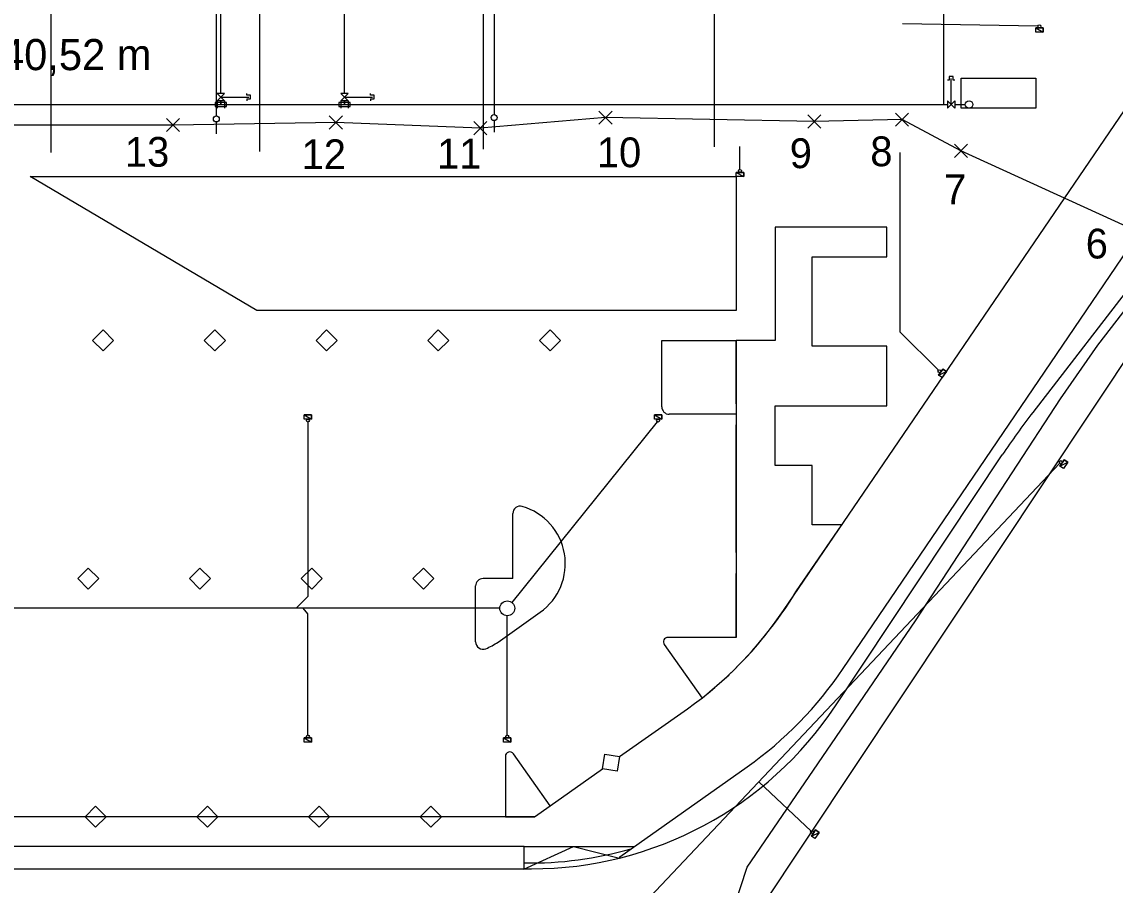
# Model space of a CAD drawing. Extents: x -263995 to -263575, y -1242437 to -1242140.
# Drawn here: x -263850 to -263776.6, y -1242302.6 to -1242244.6 of the extents above; entities that cross this region are included whole.
import ezdxf

# ---------------------------------------------------------------- set-up
doc = ezdxf.new("R2010")
doc.units = 0
for name, color, linetype in [('DELTA_ONLINE_JESTVUJUCA_TRASA', 7, 'Continuous'), ('KFA_2D_SITUACIA_DSP', 7, 'Continuous'), ('KFA_BODY', 7, 'Continuous'), ('KFA_SO_63-3_PRELOZKA_DELTA_ONLINE_TRASA', 7, 'Continuous'), ('POPIS', 7, 'Continuous')]:
    doc.layers.add(name, color=color, linetype=linetype)

msp = doc.modelspace()

# ---------------------------------------------------------------- linework, layer by layer
at = {"layer": 'DELTA_ONLINE_JESTVUJUCA_TRASA'}
for p, q in [((-263777.8, -1242266.3), (-263773.12, -1242260.22)), ((-263780.3, -1242269.92), (-263777.8, -1242266.3)), ((-263790.03, -1242284.82), (-263780.3, -1242269.92)), ((-263795.68, -1242293.09), (-263790.03, -1242284.82)), ((-263801.33, -1242301.36), (-263795.68, -1242293.09)), ((-263802.26, -1242304.18), (-263801.33, -1242301.36))]:
    msp.add_line(p, q, dxfattribs=at)
at = {"layer": 'KFA_2D_SITUACIA_DSP'}
for p, q in [((-263788.143, -1242250.14), (-263788.143, -1242140.046)), ((-263822.88, -1242337.914), (-263734.49, -1242204.937)), ((-263794.898, -1242288.032), (-263742.736, -1242211.145)), ((-263798.899, -1242284.125), (-263751.864, -1242215.081)), ((-263752.521, -1242232.37), (-263782.166, -1242270.821)), ((-263836.968, -1242235.757), (-263836.969, -1242250.909)), ((-263836.668, -1242249.39), (-263836.668, -1242235.757)), ((-263828.368, -1242249.39), (-263828.368, -1242235.757)), ((-263818.318, -1242235.757), (-263818.321, -1242250.822)), ((-263803.556, -1242238.308), (-263803.556, -1242252.989)), ((-263848.068, -1242241.132), (-263848.068, -1242253.366)), ((-263834.068, -1242241.132), (-263834.068, -1242253.298)), ((-263819.068, -1242241.132), (-263819.068, -1242253.146)), ((-263781.818, -1242244.885), (-263790.914, -1242244.718)), ((-263781.968, -1242244.987), (-263781.468, -1242244.987)), ((-263781.968, -1242245.277), (-263781.968, -1242244.987)), ((-263781.968, -1242244.987), (-263781.468, -1242245.277)), ((-263781.968, -1242244.987), (-263781.468, -1242245.277)), ((-263781.468, -1242244.987), (-263781.968, -1242244.987)), ((-263781.468, -1242245.277), (-263781.968, -1242245.277)), ((-263781.468, -1242244.987), (-263781.468, -1242245.277)), ((-263781.468, -1242245.277), (-263781.468, -1242244.987)), ((-263787.768, -1242248.265), (-263787.768, -1242248.515)), ((-263787.518, -1242248.265), (-263787.768, -1242248.265)), ((-263787.643, -1242250.14), (-263787.643, -1242248.39)), ((-263787.518, -1242248.515), (-263787.518, -1242248.265)), ((-263786.968, -1242248.382), (-263781.968, -1242248.382)), ((-263786.968, -1242250.382), (-263786.968, -1242248.382)), ((-263781.968, -1242248.382), (-263781.968, -1242250.382)), ((-263787.768, -1242248.515), (-263787.893, -1242248.515)), ((-263787.393, -1242248.515), (-263787.518, -1242248.515)), ((-263836.418, -1242249.39), (-263836.918, -1242249.39)), ((-263836.918, -1242249.89), (-263836.418, -1242249.39)), ((-263836.918, -1242249.39), (-263836.418, -1242249.89)), ((-263836.418, -1242249.89), (-263836.918, -1242249.89)), ((-263836.918, -1242249.89), (-263836.918, -1242250.39)), ((-263836.668, -1242249.64), (-263834.793, -1242249.64)), ((-263836.668, -1242250.14), (-263836.668, -1242249.89)), ((-263836.668, -1242249.89), (-263836.668, -1242250.14)), ((-263836.418, -1242249.89), (-263836.418, -1242250.39)), ((-263834.918, -1242249.515), (-263834.918, -1242249.39)), ((-263834.668, -1242249.515), (-263834.918, -1242249.515)), ((-263834.918, -1242249.765), (-263834.918, -1242249.89)), ((-263834.918, -1242249.765), (-263834.668, -1242249.765)), ((-263834.668, -1242249.765), (-263834.668, -1242249.515)), ((-263828.118, -1242249.39), (-263828.618, -1242249.39)), ((-263828.618, -1242249.89), (-263828.118, -1242249.39)), ((-263828.618, -1242249.39), (-263828.118, -1242249.89)), ((-263828.118, -1242249.89), (-263828.618, -1242249.89)), ((-263828.618, -1242249.89), (-263828.618, -1242250.39)), ((-263828.368, -1242249.64), (-263826.493, -1242249.64)), ((-263828.368, -1242250.14), (-263828.368, -1242249.89)), ((-263828.368, -1242249.89), (-263828.368, -1242250.14)), ((-263828.118, -1242249.89), (-263828.118, -1242250.39)), ((-263826.618, -1242249.515), (-263826.618, -1242249.39)), ((-263826.368, -1242249.515), (-263826.618, -1242249.515)), ((-263826.618, -1242249.765), (-263826.618, -1242249.89)), ((-263826.618, -1242249.765), (-263826.368, -1242249.765)), ((-263826.368, -1242249.765), (-263826.368, -1242249.515)), ((-263787.893, -1242250.39), (-263787.393, -1242249.89)), ((-263787.893, -1242249.89), (-263787.893, -1242250.39)), ((-263787.393, -1242250.39), (-263787.893, -1242249.89)), ((-263787.393, -1242249.89), (-263787.393, -1242250.39)), ((-263924.143, -1242250.14), (-263788.143, -1242250.14)), ((-263836.293, -1242250.015), (-263837.043, -1242250.015)), ((-263837.043, -1242250.015), (-263837.043, -1242250.265)), ((-263837.043, -1242250.265), (-263836.293, -1242250.265)), ((-263836.293, -1242250.265), (-263836.293, -1242250.015)), ((-263827.993, -1242250.015), (-263828.743, -1242250.015)), ((-263828.743, -1242250.015), (-263828.743, -1242250.265)), ((-263828.743, -1242250.265), (-263827.993, -1242250.265)), ((-263827.993, -1242250.265), (-263827.993, -1242250.015)), ((-263788.143, -1242250.14), (-263787.893, -1242250.14)), ((-263788.143, -1242250.14), (-263787.893, -1242250.14)), ((-263787.393, -1242250.14), (-263786.693, -1242250.14)), ((-263781.968, -1242250.382), (-263786.968, -1242250.382)), ((-263836.969, -1242251.309), (-263836.969, -1242252.109)), ((-263818.322, -1242251.222), (-263818.322, -1242252.009)), ((-263801.822, -1242254.497), (-263801.837, -1242252.972)), ((-263791.063, -1242265.427), (-263791.063, -1242253.362)), ((-263834.256, -1242263.984), (-263849.468, -1242254.985)), ((-263849.468, -1242254.985), (-263802.068, -1242254.987)), ((-263802.071, -1242254.697), (-263801.571, -1242254.697)), ((-263802.071, -1242254.987), (-263802.071, -1242254.697)), ((-263802.071, -1242254.697), (-263801.571, -1242254.987)), ((-263802.071, -1242254.697), (-263801.571, -1242254.987)), ((-263801.571, -1242254.697), (-263802.071, -1242254.697)), ((-263801.571, -1242254.987), (-263802.071, -1242254.987)), ((-263802.068, -1242254.987), (-263802.068, -1242263.988)), ((-263801.571, -1242254.697), (-263801.571, -1242254.987)), ((-263801.571, -1242254.987), (-263801.571, -1242254.697)), ((-263802.068, -1242263.988), (-263834.256, -1242263.984)), ((-263845.275, -1242265.986), (-263844.568, -1242265.279)), ((-263844.568, -1242265.279), (-263843.861, -1242265.986)), ((-263837.775, -1242265.986), (-263837.068, -1242265.279)), ((-263837.068, -1242265.279), (-263836.361, -1242265.986)), ((-263830.275, -1242265.986), (-263829.568, -1242265.279)), ((-263829.568, -1242265.279), (-263828.861, -1242265.986)), ((-263822.775, -1242265.986), (-263822.068, -1242265.279)), ((-263822.068, -1242265.279), (-263821.361, -1242265.986)), ((-263815.275, -1242265.986), (-263814.568, -1242265.279)), ((-263814.568, -1242265.279), (-263813.861, -1242265.986)), ((-263844.568, -1242266.693), (-263845.275, -1242265.986)), ((-263843.861, -1242265.986), (-263844.568, -1242266.693)), ((-263837.068, -1242266.693), (-263837.775, -1242265.986)), ((-263836.361, -1242265.986), (-263837.068, -1242266.693)), ((-263829.568, -1242266.693), (-263830.275, -1242265.986)), ((-263828.861, -1242265.986), (-263829.568, -1242266.693)), ((-263822.068, -1242266.694), (-263822.775, -1242265.986)), ((-263821.361, -1242265.986), (-263822.068, -1242266.694)), ((-263814.568, -1242266.693), (-263815.275, -1242265.986)), ((-263813.861, -1242265.986), (-263814.568, -1242266.693)), ((-263807.068, -1242270.447), (-263807.068, -1242265.987)), ((-263807.068, -1242265.987), (-263802.068, -1242265.987)), ((-263802.068, -1242270.24), (-263802.068, -1242265.987)), ((-263788.502, -1242267.989), (-263791.063, -1242265.427)), ((-263788.491, -1242268.322), (-263788.207, -1242267.91)), ((-263788.207, -1242267.91), (-263788.491, -1242268.322)), ((-263788.491, -1242268.322), (-263787.968, -1242268.075)), ((-263788.491, -1242268.322), (-263787.968, -1242268.075)), ((-263787.968, -1242268.075), (-263788.252, -1242268.487)), ((-263788.207, -1242267.91), (-263787.968, -1242268.075)), ((-263787.968, -1242268.075), (-263788.207, -1242267.91)), ((-263788.252, -1242268.487), (-263788.491, -1242268.322)), ((-263831.074, -1242270.983), (-263830.574, -1242270.983)), ((-263831.074, -1242271.273), (-263831.074, -1242270.983)), ((-263831.074, -1242270.983), (-263830.574, -1242271.273)), ((-263831.074, -1242270.983), (-263830.574, -1242271.273)), ((-263830.574, -1242270.983), (-263831.074, -1242270.983)), ((-263830.574, -1242270.983), (-263830.574, -1242271.273)), ((-263830.574, -1242271.273), (-263830.574, -1242270.983)), ((-263807.568, -1242270.982), (-263807.068, -1242270.982)), ((-263807.568, -1242271.272), (-263807.568, -1242270.982)), ((-263807.568, -1242270.982), (-263807.068, -1242271.272)), ((-263807.568, -1242270.982), (-263807.068, -1242271.272)), ((-263807.068, -1242270.982), (-263807.568, -1242270.982)), ((-263807.068, -1242270.982), (-263807.068, -1242271.272)), ((-263807.068, -1242271.272), (-263807.068, -1242270.982)), ((-263802.068, -1242270.947), (-263806.568, -1242270.947)), ((-263830.574, -1242271.273), (-263831.074, -1242271.273)), ((-263830.824, -1242271.473), (-263830.824, -1242283.187)), ((-263807.38, -1242271.45), (-263817.128, -1242283.593)), ((-263807.068, -1242271.272), (-263807.568, -1242271.272)), ((-263802.068, -1242280.24), (-263802.068, -1242271.654)), ((-263795.416, -1242290.541), (-263784.214, -1242273.68)), ((-263780.34, -1242274.426), (-263780.062, -1242274.011)), ((-263780.062, -1242274.011), (-263780.34, -1242274.426)), ((-263780.062, -1242274.011), (-263779.821, -1242274.173)), ((-263779.821, -1242274.173), (-263780.062, -1242274.011)), ((-263780.353, -1242274.236), (-263808.248, -1242303.783)), ((-263780.34, -1242274.426), (-263779.821, -1242274.173)), ((-263780.34, -1242274.426), (-263779.821, -1242274.173)), ((-263780.099, -1242274.588), (-263780.34, -1242274.426)), ((-263779.821, -1242274.173), (-263780.099, -1242274.588)), ((-263817.068, -1242281.982), (-263817.068, -1242277.62)), ((-263846.275, -1242281.982), (-263845.568, -1242281.275)), ((-263845.568, -1242281.275), (-263844.861, -1242281.982)), ((-263838.775, -1242281.982), (-263838.068, -1242281.275)), ((-263838.068, -1242281.275), (-263837.361, -1242281.982)), ((-263831.275, -1242281.982), (-263830.568, -1242281.275)), ((-263830.568, -1242281.275), (-263829.861, -1242281.982)), ((-263823.775, -1242281.982), (-263823.068, -1242281.275)), ((-263823.068, -1242281.275), (-263822.361, -1242281.982)), ((-263845.568, -1242282.689), (-263846.275, -1242281.982)), ((-263844.861, -1242281.982), (-263845.568, -1242282.689)), ((-263838.068, -1242282.689), (-263838.775, -1242281.982)), ((-263837.361, -1242281.982), (-263838.068, -1242282.689)), ((-263830.568, -1242282.689), (-263831.275, -1242281.982)), ((-263829.861, -1242281.982), (-263830.568, -1242282.689)), ((-263823.068, -1242282.689), (-263823.775, -1242281.982)), ((-263822.361, -1242281.982), (-263823.068, -1242282.689)), ((-263817.068, -1242281.982), (-263819.068, -1242281.982)), ((-263802.068, -1242285.947), (-263802.068, -1242281.654)), ((-263819.568, -1242286.231), (-263819.568, -1242282.482)), ((-263830.824, -1242283.187), (-263831.619, -1242283.982)), ((-263817.941, -1242283.982), (-263870.324, -1242283.982)), ((-263817.941, -1242283.982), (-263870.324, -1242283.982)), ((-263830.824, -1242284.343), (-263831.149, -1242283.982)), ((-263830.824, -1242292.492), (-263830.824, -1242284.343)), ((-263818.06, -1242286.248), (-263815.232, -1242284.248)), ((-263817.441, -1242292.492), (-263817.441, -1242284.482)), ((-263809.895, -1242293.947), (-263805.344, -1242290.728)), ((-263831.074, -1242292.693), (-263830.574, -1242292.693)), ((-263831.074, -1242292.983), (-263831.074, -1242292.693)), ((-263831.074, -1242292.693), (-263830.574, -1242292.983)), ((-263831.074, -1242292.693), (-263830.574, -1242292.983)), ((-263830.574, -1242292.693), (-263831.074, -1242292.693)), ((-263830.574, -1242292.983), (-263831.074, -1242292.983)), ((-263830.824, -1242292.693), (-263830.824, -1242292.692)), ((-263830.574, -1242292.693), (-263830.574, -1242292.983)), ((-263830.574, -1242292.983), (-263830.574, -1242292.693)), ((-263817.691, -1242292.692), (-263817.191, -1242292.692)), ((-263817.691, -1242292.982), (-263817.691, -1242292.692)), ((-263817.691, -1242292.692), (-263817.191, -1242292.982)), ((-263817.691, -1242292.692), (-263817.191, -1242292.982)), ((-263817.191, -1242292.692), (-263817.691, -1242292.692)), ((-263817.191, -1242292.982), (-263817.691, -1242292.982)), ((-263817.191, -1242292.692), (-263817.191, -1242292.982)), ((-263817.191, -1242292.982), (-263817.191, -1242292.692)), ((-263811.05, -1242294.763), (-263810.881, -1242293.778)), ((-263810.881, -1242293.778), (-263809.895, -1242293.947)), ((-263809.895, -1242293.947), (-263810.064, -1242294.932)), ((-263809.875, -1242300.669), (-263801.342, -1242294.634)), ((-263814.555, -1242297.242), (-263811.05, -1242294.763)), ((-263810.064, -1242294.932), (-263811.05, -1242294.763)), ((-263797.048, -1242298.952), (-263800.558, -1242295.638)), ((-263845.775, -1242297.982), (-263845.068, -1242297.275)), ((-263845.068, -1242297.275), (-263844.361, -1242297.982)), ((-263838.275, -1242297.982), (-263837.568, -1242297.275)), ((-263837.568, -1242297.275), (-263836.861, -1242297.982)), ((-263830.775, -1242297.982), (-263830.068, -1242297.275)), ((-263830.068, -1242297.275), (-263829.361, -1242297.982)), ((-263823.275, -1242297.982), (-263822.568, -1242297.275)), ((-263822.568, -1242297.275), (-263821.861, -1242297.982)), ((-263815.601, -1242297.982), (-263917.08, -1242297.982)), ((-263845.068, -1242298.689), (-263845.775, -1242297.982)), ((-263844.361, -1242297.982), (-263845.068, -1242298.689)), ((-263837.568, -1242298.689), (-263838.275, -1242297.982)), ((-263836.861, -1242297.982), (-263837.568, -1242298.689)), ((-263830.068, -1242298.689), (-263830.775, -1242297.982)), ((-263829.361, -1242297.982), (-263830.068, -1242298.689)), ((-263822.568, -1242298.689), (-263823.275, -1242297.982)), ((-263821.861, -1242297.982), (-263822.568, -1242298.689)), ((-263797.029, -1242299.286), (-263796.75, -1242298.871)), ((-263796.75, -1242298.871), (-263797.029, -1242299.286)), ((-263797.029, -1242299.286), (-263796.51, -1242299.032)), ((-263797.029, -1242299.286), (-263796.51, -1242299.032)), ((-263796.51, -1242299.032), (-263796.788, -1242299.448)), ((-263796.75, -1242298.871), (-263796.51, -1242299.032)), ((-263796.51, -1242299.032), (-263796.75, -1242298.871)), ((-263796.788, -1242299.448), (-263797.029, -1242299.286)), ((-263816.308, -1242299.982), (-263918.049, -1242299.982)), ((-263816.327, -1242301.51), (-263813.002, -1242299.982)), ((-263816.308, -1242301.482), (-263816.308, -1242299.982)), ((-263816.308, -1242299.982), (-263808.904, -1242299.982)), ((-263813.002, -1242299.982), (-263809.906, -1242300.757)), ((-263809.906, -1242300.757), (-263809.875, -1242300.669)), ((-263914.08, -1242301.482), (-263815.822, -1242301.482))]:
    msp.add_line(p, q, dxfattribs=at)
for points in [[(-263798.064, -1242282.882), (-263794.987, -1242278.383), (-263796.968, -1242278.382), (-263796.968, -1242274.382), (-263799.468, -1242274.382), (-263799.468, -1242270.382), (-263791.968, -1242270.382), (-263791.968, -1242266.382), (-263796.968, -1242266.382), (-263796.968, -1242260.382), (-263791.968, -1242260.382), (-263791.968, -1242258.382), (-263799.468, -1242258.382), (-263799.468, -1242265.987), (-263802.068, -1242265.987)], [(-263802.068, -1242265.987), (-263802.068, -1242270.24), (-263802.068, -1242270.947), (-263802.068, -1242271.654), (-263802.068, -1242273.447), (-263802.068, -1242275.947), (-263802.068, -1242278.447), (-263802.068, -1242280.24), (-263802.068, -1242280.24), (-263802.068, -1242281.654), (-263802.068, -1242283.447), (-263802.068, -1242285.947), (-263806.656, -1242285.943)], [(-263806.901, -1242286.416), (-263804.349, -1242290.024), (-263802.552, -1242288.44)], [(-263817.568, -1242293.926), (-263817.568, -1242297.982), (-263815.601, -1242297.982), (-263814.555, -1242297.242), (-263817.023, -1242293.753)]]:
    msp.add_lwpolyline(points, dxfattribs=at)
for centre, radius in [((-263781.718, -1242244.887), 0.1), ((-263786.443, -1242250.14), 0.25), ((-263836.969, -1242251.109), 0.2), ((-263818.322, -1242251.022), 0.2), ((-263801.821, -1242254.597), 0.1), ((-263788.431, -1242268.059), 0.1), ((-263830.824, -1242271.373), 0.1), ((-263807.318, -1242271.372), 0.1), ((-263780.284, -1242274.163), 0.1), ((-263817.441, -1242283.982), 0.5), ((-263830.824, -1242292.592), 0.1), ((-263817.441, -1242292.592), 0.1), ((-263796.975, -1242299.02), 0.1)]:
    msp.add_circle(centre, radius, dxfattribs=at)
for centre, radius, start, end in [((-263806.568, -1242270.447), 0.5, 180, 270), ((-263742.568, -1242301.35), 50, 142.36875, 146.39918), ((-263816.568, -1242277.62), 0.5, 73.84458, 180), ((-263817.542, -1242280.982), 4, 305.27024, 73.84458), ((-263819.068, -1242282.482), 0.5, 90, 180), ((-263821.806, -1242268.304), 27.86, 313.71918, 328.45017), ((-263820.069, -1242269.909), 25.5, 305.27024, 326.11647), ((-263819.068, -1242286.231), 0.5, 180, 291.83316), ((-263820.369, -1242282.982), 4, 291.83316, 305.27024), ((-263806.656, -1242286.243), 0.3, 89.94357, 215.27024), ((-263816.067, -1242273.815), 25.5, 305.27024, 326.11647), ((-263815.822, -1242276.982), 24.5, 270, 326.39918), ((-263817.268, -1242293.926), 0.3, 35.27024, 180), ((-263815.836, -1242276.967), 24.119, 268.87866, 286.17976)]:
    msp.add_arc(centre, radius, start, end, dxfattribs=at)
at = {"layer": 'KFA_BODY'}
for p, q in [((-263811.285, -1242251.461), (-263810.401, -1242250.577)), ((-263810.401, -1242251.461), (-263811.285, -1242250.577)), ((-263840.315, -1242251.962), (-263839.431, -1242251.078)), ((-263839.431, -1242251.962), (-263840.315, -1242251.078)), ((-263829.39, -1242251.795), (-263828.506, -1242250.911)), ((-263828.506, -1242251.795), (-263829.39, -1242250.911)), ((-263819.691, -1242252.171), (-263818.807, -1242251.287)), ((-263818.807, -1242252.171), (-263819.691, -1242251.287)), ((-263797.273, -1242251.724), (-263796.389, -1242250.84)), ((-263796.389, -1242251.724), (-263797.273, -1242250.84)), ((-263791.382, -1242251.597), (-263790.498, -1242250.713)), ((-263790.498, -1242251.597), (-263791.382, -1242250.713)), ((-263787.431, -1242253.693), (-263786.547, -1242252.809)), ((-263786.547, -1242253.693), (-263787.431, -1242252.809))]:
    msp.add_line(p, q, dxfattribs=at)
at = {"layer": 'KFA_SO_63-3_PRELOZKA_DELTA_ONLINE_TRASA'}
for points in [[(-263786.989, -1242253.251), (-263790.94, -1242251.155), (-263796.831, -1242251.282), (-263810.843, -1242251.019), (-263819.249, -1242251.729), (-263828.948, -1242251.353), (-263839.873, -1242251.52), (-263855.379, -1242251.533), (-263870.851, -1242251.493), (-263884.513, -1242251.425), (-263895.724, -1242251.49), (-263903.83, -1242251.49), (-263915.205, -1242251.485), (-263919.446, -1242251.469)], [(-263770.383, -1242255.549), (-263772.055, -1242258.017), (-263773.15, -1242258.989), (-263774.214, -1242259.11), (-263775.866, -1242258.328), (-263786.989, -1242253.251)]]:
    msp.add_lwpolyline(points, dxfattribs=at)

# ---------------------------------------------------------------- texts
at = {"layer": 'KFA_BODY'}
for s, p in [('13', (-263843.102, -1242254.321)), ('12', (-263831.241, -1242254.482)), ('11', (-263822.155, -1242254.441)), ('10', (-263811.424, -1242254.353)), ('9', (-263798.478, -1242254.415)), ('8', (-263793.071, -1242254.285)), ('7', (-263788.119, -1242256.835)), ('6', (-263778.611, -1242260.482))]:
    msp.add_text(s, height=2, dxfattribs=at).set_placement(p)
at = {"layer": 'POPIS'}
msp.add_text('Prípojka Delta Online, dĺžka - 240,52 m', height=2.09, dxfattribs=at).set_placement((-263889.945, -1242247.833))

doc.saveas('drawing.dxf')
